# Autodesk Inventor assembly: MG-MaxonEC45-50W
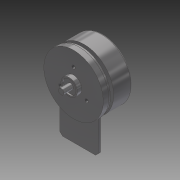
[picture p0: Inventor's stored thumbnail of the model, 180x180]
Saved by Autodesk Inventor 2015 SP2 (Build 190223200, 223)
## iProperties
Created: 2015-08
Part Number: MG-MaxonEC45-50W
Document SubType Name: Assembly
Designer: ryll
Author: ryll
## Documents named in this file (3)
- E:\TIGERs GIT\Hardware\mechanik\2016\Inventor\Kaufteile\MG-MaxonEC45-50W.iam
- E:\TIGERs GIT\Hardware\mechanik\2016\Inventor\Kaufteile\MaxonEC45-50W.ipt
- E:\TIGERs GIT\Hardware\mechanik\2016\Inventor\Kaufteile\Molex MiniFit 8pol.ipt
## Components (2 placed, 2 different names)
1. MaxonEC45-50W:1 — Passend:1, Fluchtend:1, Fluchtend:2
2. Molex MiniFit 8pol:1 — Passend:1, Fluchtend:1, Fluchtend:2
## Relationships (3: Flush 2, Mate 1)
- Passend:1 [Mate]: MaxonEC45-50W:1 ↔ Molex MiniFit 8pol:1
- Fluchtend:1 [Flush]: MaxonEC45-50W:1 ↔ Molex MiniFit 8pol:1
- Fluchtend:2 [Flush]: MaxonEC45-50W:1 ↔ Molex MiniFit 8pol:1
